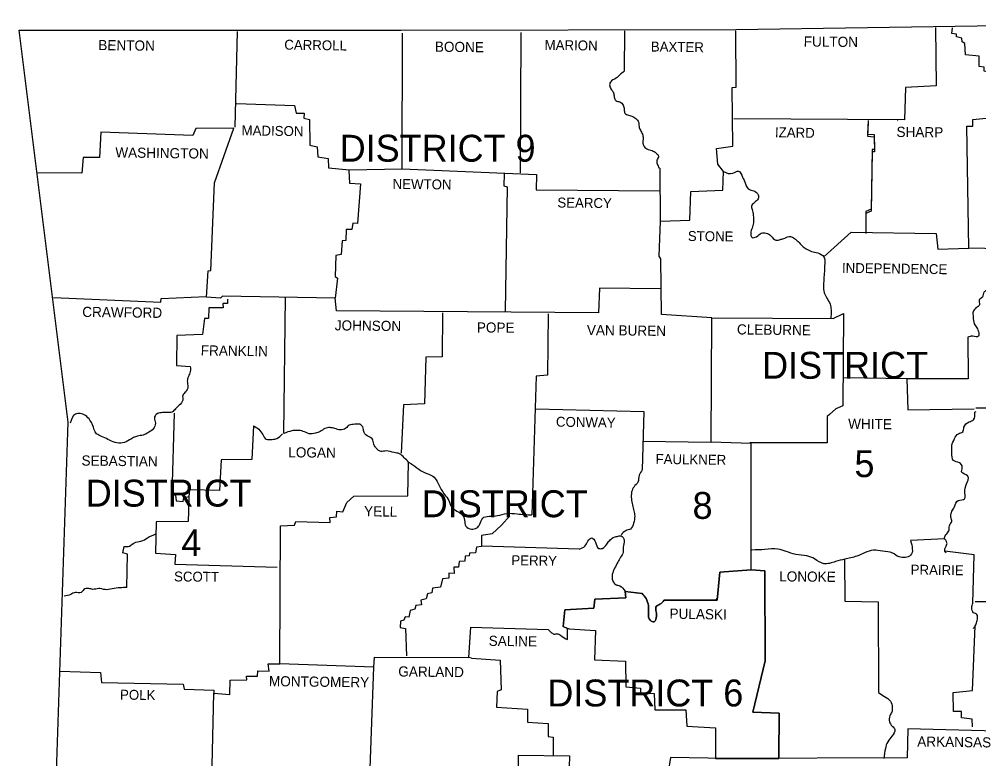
# Model space of a CAD drawing. Extents: x 1096785 to 1382432, y 216169 to 341661.
# Drawn here: x 1229111 to 1237243, y 286360 to 292630 of the extents above; entities that cross this region are included whole.
import ezdxf

# ---------------------------------------------------------------- set-up
doc = ezdxf.new("R2010")
doc.units = 0
for name, color, linetype in [('1', 7, 'Continuous'), ('21', 7, 'Continuous'), ('3', 7, 'Continuous')]:
    doc.layers.add(name, color=color, linetype=linetype)

msp = doc.modelspace()

# ---------------------------------------------------------------- linework, layer by layer
at = {"layer": '1'}
for p, q in [((1237219.2, 289336.3), (1237457.2, 289336.3)), ((1233771.2, 287462.3), (1233757.2, 287464.3)), ((1233757.2, 287464.3), (1233771.2, 287462.3)), ((1232945.2, 287214.3), (1232921.2, 287218.3)), ((1233635.2, 286396.3), (1233635, 286386.2)), ((1235011.2, 286364.3), (1235011.2, 286363.9)), ((1235011.2, 286364.3), (1235011.2, 286363.9)), ((1235011.2, 286363.9), (1235107.2, 286362.3)), ((1235107.2, 286362.3), (1235549.2, 286364)), ((1235549.2, 286378.3), (1235549.2, 286364)), ((1235549.2, 286364), (1235549.2, 286378.3))]:
    msp.add_line(p, q, dxfattribs=at)
for points in [[(1229111.2, 292538.3), (1232345.2, 292536.3), (1235183.2, 292542.3), (1238531.2, 292594.3), (1240083.2, 292630.3)], [(1229345.2, 283788.3), (1229525.2, 289214.3), (1229111.2, 292538.3)], [(1230957.2, 292526.3), (1230939.2, 291716.3)], [(1230953.2, 291914.3), (1231445.2, 291898.3), (1231457.2, 291834.3), (1231525.2, 291832.3), (1231523.2, 291792.3), (1231571.2, 291780.3), (1231575.2, 291562.3), (1231637.2, 291548.3), (1231641.2, 291462.3), (1231729.2, 291450.3), (1231733.2, 291370.3), (1231907.2, 291352.3), (1232355.2, 291362.3), (1232359.2, 292512.3)], [(1233361.2, 292516.3), (1233355.2, 291328.3)], [(1234241.2, 292530.3), (1234237.2, 292188.3)], [(1234577.2, 287704.3), (1235027.2, 287706.3), (1235047.2, 287942.3), (1235315.2, 287962.3), (1235315.2, 289034.3), (1234975.2, 289044.3), (1234981.2, 290098.3), (1234553.2, 290126.3), (1234547.2, 290598.3), (1234533.2, 290622.3), (1234545.2, 290918.3), (1234793.2, 290926.3), (1234803.2, 291170.3), (1235075.2, 291180.3), (1235079.2, 291338.3), (1235031.2, 291400.3), (1235019.2, 291534.3), (1235159.2, 291554.3), (1235153.2, 292052.3), (1235187.2, 292054.3), (1235183.2, 292530.3)], [(1236877.2, 292560.3), (1236881.2, 292064.3), (1236621.2, 292050.3), (1236613.2, 291778.3), (1235167.2, 291786.3)], [(1237443.2, 289324.3), (1237453.2, 289054.3), (1237979.2, 289068.3), (1237965.2, 290672.3), (1237159.2, 290690.3), (1237141.2, 291722.3), (1237193.2, 291724.3), (1237191.2, 291780.3), (1237361.2, 291796.3), (1237353.2, 292058.3), (1237321.2, 292064.3), (1237323.2, 292180.3), (1237287.2, 292190.3), (1237287.2, 292224.3), (1237245.2, 292230.3), (1237245.2, 292316.3), (1237131.2, 292328.3), (1237125.2, 292424.3), (1237103.2, 292438.3), (1237099.2, 292470.3), (1237053.2, 292480.3), (1237055.2, 292504.3), (1237015.2, 292510.3), (1237021.2, 292558.3)], [(1231799.2, 290158.3), (1231789.2, 290264.3), (1230835.2, 290282.3), (1230817.2, 290264.3), (1230699.2, 290274.3), (1230711.2, 290498.3), (1230735.2, 290500.3), (1230767.2, 291242.3), (1230929.2, 291706.3), (1230607.2, 291704.3), (1230583.2, 291644.3), (1229803.2, 291672.3), (1229791.2, 291458.3), (1229653.2, 291458.3), (1229643.2, 291326.3), (1229269.2, 291328.3)], [(1236305.2, 291772.3), (1236301.2, 291656.3), (1236357.2, 291652.3), (1236359.2, 291524.3), (1236339.2, 291524.3), (1236331.2, 291020.3), (1236285.2, 291000.3), (1236285.2, 290832.3)], [(1236305.2, 291754.3), (1236301.2, 291638.3), (1236357.2, 291634.3), (1236359.2, 291506.3), (1236339.2, 291506.3), (1236331.2, 291002.3), (1236285.2, 290982.3), (1236285.2, 290814.3)], [(1236555.2, 291768.3), (1236557.2, 291770.3)], [(1234545.2, 290918.3), (1234543.2, 291368.3)], [(1231903.2, 291348.3), (1231911.2, 291240.3), (1232003.2, 291234.3), (1231979.2, 290898.3), (1231937.2, 290900.3), (1231929.2, 290846.3), (1231881.2, 290846.3), (1231879.2, 290754.3), (1231849.2, 290752.3), (1231839.2, 290634.3), (1231795.2, 290628.3), (1231789.2, 290448.3), (1231809.2, 290434.3), (1231789.2, 290264.3)], [(1232355.2, 291362.3), (1233495.2, 291314.3), (1233493.2, 291184.3), (1234539.2, 291176.3)], [(1233221.2, 291320.3), (1233219.2, 291216.3), (1233245.2, 291210.3), (1233229.2, 290154.3)], [(1235933.2, 290618.3), (1236161.2, 290824.3), (1236881.2, 290814.3), (1236895.2, 290680.3), (1237157.2, 290690.3)], [(1234545.2, 290344.3), (1234029.2, 290350.3), (1234019.2, 290140.3), (1231799.2, 290158.3)], [(1229401.2, 290272.3), (1230311.2, 290230.3), (1230315.2, 290262.3), (1230695.2, 290280.3)], [(1230875.2, 290256.3), (1230875.2, 290220.3), (1230837.2, 290220.3), (1230839.2, 290184.3), (1230717.2, 290182.3), (1230715.2, 290092.3), (1230681.2, 290092.3), (1230663.2, 289958.3), (1230447.2, 289948.3), (1230445.2, 289694.3), (1230561.2, 289686.3)], [(1231355.2, 289118.3), (1231369.2, 290272.3)], [(1232697.2, 290142.3), (1232695.2, 289768.3), (1232557.2, 289766.3), (1232545.2, 289368.3), (1232369.2, 289362.3), (1232349.2, 288950.3)], [(1233593.2, 290132.3), (1233589.2, 289612.3), (1233493.2, 289604.3), (1233455.2, 288428.3)], [(1234981.2, 290098.3), (1236009.2, 290092.3), (1236097.2, 290134.3), (1236091.2, 289352.3), (1236031.2, 289326.3), (1235977.2, 289280.3), (1235959.2, 289262.3), (1235957.2, 289038.3), (1235303.2, 289038.3)], [(1237149.2, 289934.3), (1237153.2, 289582.3), (1236633.2, 289580.3), (1236099.2, 289590.3)], [(1236633.2, 289580.3), (1236641.2, 289318.3), (1237203.2, 289328.3)], [(1230425.2, 289290.3), (1230405.2, 288602.3), (1230435.2, 288594.3), (1230441.2, 288546.3), (1230501.2, 288542.3), (1230507.2, 288576.3), (1230555.2, 288584.3)], [(1233489.2, 289326.3), (1234403.2, 289304.3), (1234391.2, 288810.3)], [(1237219.2, 289302.3), (1237209.2, 289300.3)], [(1231097.2, 289182.3), (1231083.2, 288896.3), (1230823.2, 288894.3), (1230809.2, 288634.3), (1230551.2, 288640.3), (1230543.2, 288372.3), (1230273.2, 288370.3), (1230265.2, 288102.3), (1230435.2, 288092.3), (1230429.2, 288010.3), (1231297.2, 287986.3)], [(1234393.2, 289052.3), (1234975.2, 289044.3)], [(1237979.2, 289068.3), (1238009.2, 287972.3), (1237533.2, 287970.3), (1237531.2, 287926.3), (1237393.2, 287918.3), (1237381.2, 287690.3), (1237213.2, 287690.3)], [(1230739.2, 285932.3), (1230761.2, 286916.3), (1230897.2, 286904.3), (1230899.2, 287026.3), (1231039.2, 287030.3), (1231037.2, 287062.3), (1231131.2, 287062.3), (1231133.2, 287106.3), (1231229.2, 287104.3), (1231221.2, 287164.3), (1231321.2, 287166.3), (1231325.2, 288336.3), (1231445.2, 288340.3), (1231455.2, 288372.3), (1231745.2, 288364.3), (1231743.2, 288406.3), (1231801.2, 288412.3), (1231803.2, 288458.3), (1231853.2, 288454.3), (1231887.2, 288534.3), (1231947.2, 288586.3), (1232403.2, 288588.3), (1232411.2, 288876.3)], [(1233269.2, 288420.3), (1233197.2, 288342.3), (1233119.2, 288268.3), (1233029.2, 288254.3), (1233029.2, 288160.3), (1232985.2, 288154.3), (1232977.2, 288106.3), (1232927.2, 288102.3), (1232923.2, 288080.3), (1232889.2, 288078.3), (1232887.2, 288036.3), (1232839.2, 288034.3), (1232835.2, 287986.3), (1232795.2, 287986.3), (1232797.2, 287930.3), (1232753.2, 287934.3), (1232751.2, 287890.3), (1232697.2, 287886.3), (1232681.2, 287814.3), (1232613.2, 287808.3), (1232607.2, 287768.3), (1232571.2, 287758.3), (1232561.2, 287716.3), (1232515.2, 287706.3), (1232519.2, 287664.3), (1232473.2, 287660.3), (1232465.2, 287628.3), (1232423.2, 287616.3), (1232413.2, 287562.3), (1232381.2, 287564.3), (1232371.2, 287536.3), (1232341.2, 287526.3), (1232339.2, 287472.3), (1232385.2, 287464.3), (1232393.2, 287232.3)], [(1236955.2, 288224.3), (1236665.2, 288210.3)], [(1230023.2, 287812.3), (1230029.2, 288094.3), (1229989.2, 288106.3), (1230001.2, 288160.3)], [(1233855.2, 288136.3), (1233031.2, 288162.3)], [(1237191.2, 287680.3), (1237205.2, 288088.3), (1236955.2, 288120.3)], [(1236105.2, 288054.3), (1236109.2, 287696.3), (1236391.2, 287690.3), (1236393.2, 286922.3)], [(1235315.2, 287962.3), (1235047.2, 287942.3), (1235027.2, 287706.3), (1234577.2, 287704.3)], [(1235315.2, 287962.3), (1235431.2, 287954.3), (1235433.2, 287190.3), (1235329.2, 286756.3), (1235551.2, 286746.3), (1235549.2, 286378.3)], [(1235549.2, 286378.3), (1235551.2, 286746.3), (1235329.2, 286756.3), (1235433.2, 287190.3), (1235431.2, 287954.3), (1235315.2, 287962.3)], [(1233757.2, 287372.3), (1233757.2, 287464.3), (1233721.2, 287482.3), (1233735.2, 287622.3), (1233981.2, 287636.3), (1233989.2, 287714.3), (1234251.2, 287724.3), (1234245.2, 287778.3), (1234389.2, 287762.3)], [(1234389.2, 287762.3), (1234245.2, 287778.3), (1234251.2, 287724.3), (1233989.2, 287714.3), (1233981.2, 287636.3), (1233735.2, 287622.3), (1233721.2, 287482.3), (1233757.2, 287464.3)], [(1235017.2, 287708.3), (1235027.2, 287718.3)], [(1232117.2, 287136.3), (1232121.2, 287222.3), (1232921.2, 287218.3), (1232939.2, 287476.3), (1233593.2, 287456.3)], [(1237189.2, 286630.3), (1237187.2, 286696.3), (1237097.2, 286706.3), (1237095.2, 286762.3), (1237029.2, 286760.3), (1237025.2, 286922.3), (1237189.2, 286940.3), (1237213.2, 287488.3)], [(1233771.2, 287462.3), (1233995.2, 287448.3), (1233987.2, 287198.3), (1234249.2, 287188.3), (1234253.2, 286970.3), (1234377.2, 286960.3), (1234377.2, 286922.3), (1234493.2, 286914.3), (1234497.2, 286774.3), (1234761.2, 286774.3), (1234769.2, 286636.3), (1235013.2, 286624.3), (1235011.2, 286364.3)], [(1233771.2, 287462.3), (1233995.2, 287448.3), (1233987.2, 287198.3), (1234249.2, 287188.3), (1234253.2, 286970.3), (1234377.2, 286960.3), (1234377.2, 286922.3), (1234493.2, 286914.3), (1234497.2, 286774.3), (1234761.2, 286774.3), (1234769.2, 286636.3), (1235013.2, 286624.3), (1235011.2, 286364.3)], [(1232945.2, 287214.3), (1233187.2, 287196.3), (1233195.2, 286944.3), (1233161.2, 286932.3), (1233157.2, 286798.3), (1233419.2, 286780.3), (1233419.2, 286670.3), (1233593.2, 286660.3), (1233595.2, 286550.3), (1233637.2, 286544.3), (1233635.2, 286396.3)], [(1229455.2, 287104.3), (1229801.2, 287092.3), (1229809.2, 287008.3), (1230501.2, 286994.3), (1230509.2, 286950.3), (1230761.2, 286942.3), (1230759.2, 286904.3)], [(1232071.2, 285890.3), (1232117.2, 287136.3)], [(1237397.2, 286594.3), (1236641.2, 286614.3), (1236637.2, 286368.3), (1235107.2, 286362.3)], [(1232085.2, 286056.3), (1233229.2, 286040.3), (1233251.2, 286230.3), (1233341.2, 286230.3), (1233343.2, 286390.3), (1233775.2, 286384.3), (1233771.2, 286288.3), (1233883.2, 286280.3), (1233883.2, 286104.3), (1233955.2, 286098.3)], [(1235107.2, 286362.3), (1234629.2, 286370.3), (1234611.2, 286248.3), (1234145.2, 286234.3), (1234141.2, 286194.3), (1234075.2, 286182.3), (1234067.2, 286114.3), (1233955.2, 286098.3)]]:
    msp.add_lwpolyline(points, dxfattribs=at)
for points in [[(1234237.2, 292188.3), (1234201.2, 292158.3), (1234169.2, 292130.3), (1234121.2, 292096.3), (1234115.2, 292064.3), (1234131.2, 292032.3), (1234147.2, 292006.3), (1234153.2, 291970.3), (1234167.2, 291940.3), (1234201.2, 291928.3), (1234229.2, 291902.3), (1234239.2, 291866.3), (1234243.2, 291832.3), (1234275.2, 291816.3), (1234311.2, 291804.3), (1234345.2, 291780.3), (1234361.2, 291750.3), (1234365.2, 291712.3), (1234379.2, 291682.3), (1234395.2, 291646.3), (1234399.2, 291616.3), (1234395.2, 291586.3), (1234403.2, 291558.3), (1234429.2, 291530.3), (1234475.2, 291516.3), (1234507.2, 291496.3), (1234529.2, 291468.3), (1234515.2, 291434.3), (1234517.2, 291404.3), (1234535.2, 291368.3)], [(1235079.2, 291338.3), (1235159.2, 291324.3), (1235207.2, 291342.3), (1235241.2, 291290.3), (1235259.2, 291250.3), (1235289.2, 291192.3), (1235337.2, 291174.3), (1235373.2, 291142.3), (1235373.2, 291108.3), (1235341.2, 291076.3), (1235317.2, 291044.3), (1235325.2, 291006.3), (1235333.2, 290954.3), (1235333.2, 290904.3), (1235321.2, 290858.3), (1235311.2, 290816.3), (1235321.2, 290780.3), (1235359.2, 290786.3), (1235399.2, 290816.3), (1235441.2, 290816.3), (1235481.2, 290794.3), (1235523.2, 290756.3), (1235565.2, 290764.3), (1235599.2, 290774.3), (1235647.2, 290788.3), (1235681.2, 290770.3), (1235711.2, 290746.3), (1235747.2, 290708.3), (1235781.2, 290684.3), (1235825.2, 290662.3), (1235879.2, 290648.3), (1235929.2, 290614.3), (1235937.2, 290556.3), (1235935.2, 290506.3), (1235931.2, 290444.3), (1235927.2, 290376.3), (1235933.2, 290310.3), (1235955.2, 290266.3), (1235983.2, 290214.3), (1235991.2, 290166.3), (1235989.2, 290090.3)], [(1237507.2, 290654.3), (1237483.2, 290592.3), (1237455.2, 290532.3), (1237437.2, 290480.3), (1237399.2, 290450.3), (1237387.2, 290422.3), (1237353.2, 290410.3), (1237327.2, 290370.3), (1237315.2, 290334.3), (1237287.2, 290318.3), (1237273.2, 290274.3), (1237247.2, 290250.3), (1237249.2, 290210.3), (1237219.2, 290182.3), (1237195.2, 290150.3), (1237195.2, 290106.3), (1237205.2, 290048.3), (1237225.2, 290014.3), (1237243.2, 289970.3), (1237241.2, 289942.3), (1237191.2, 289942.3), (1237149.2, 289934.3)], [(1230561.2, 289686.3), (1230561.2, 289644.3), (1230545.2, 289600.3), (1230535.2, 289562.3), (1230541.2, 289512.3), (1230523.2, 289472.3), (1230497.2, 289440.3), (1230497.2, 289400.3), (1230467.2, 289358.3), (1230435.2, 289326.3), (1230407.2, 289300.3), (1230357.2, 289296.3), (1230315.2, 289294.3), (1230273.2, 289280.3), (1230257.2, 289250.3), (1230265.2, 289204.3), (1230249.2, 289160.3), (1230207.2, 289126.3), (1230161.2, 289104.3), (1230113.2, 289096.3), (1230047.2, 289064.3), (1229987.2, 289038.3), (1229923.2, 289042.3), (1229863.2, 289068.3), (1229809.2, 289092.3), (1229767.2, 289116.3), (1229733.2, 289190.3), (1229711.2, 289230.3), (1229673.2, 289270.3), (1229627.2, 289286.3), (1229589.2, 289282.3), (1229543.2, 289204.3)], [(1236965.2, 288106.3), (1236955.2, 288120.3), (1236967.2, 288164.3), (1236973.2, 288192.3), (1236953.2, 288232.3), (1236971.2, 288266.3), (1236991.2, 288302.3), (1236997.2, 288344.3), (1237013.2, 288372.3), (1237007.2, 288408.3), (1237015.2, 288458.3), (1237037.2, 288496.3), (1237069.2, 288550.3), (1237123.2, 288564.3), (1237127.2, 288586.3), (1237125.2, 288636.3), (1237147.2, 288710.3), (1237155.2, 288736.3), (1237147.2, 288760.3), (1237099.2, 288788.3), (1237103.2, 288830.3), (1237079.2, 288870.3), (1237029.2, 288888.3), (1237015.2, 288956.3), (1237015.2, 289016.3), (1237037.2, 289074.3), (1237071.2, 289116.3), (1237107.2, 289132.3), (1237117.2, 289172.3), (1237161.2, 289216.3), (1237199.2, 289234.3), (1237209.2, 289300.3)], [(1231097.2, 289182.3), (1231141.2, 289154.3), (1231175.2, 289108.3), (1231205.2, 289070.3), (1231255.2, 289068.3), (1231295.2, 289076.3), (1231341.2, 289116.3)], [(1232411.2, 288876.3), (1232373.2, 288912.3), (1232333.2, 288946.3), (1232289.2, 288956.3), (1232221.2, 288970.3), (1232177.2, 288966.3), (1232151.2, 288978.3), (1232133.2, 288998.3), (1232115.2, 289028.3), (1232105.2, 289070.3), (1232071.2, 289092.3), (1232033.2, 289126.3), (1232027.2, 289162.3), (1231997.2, 289196.3), (1231955.2, 289196.3), (1231907.2, 289188.3), (1231879.2, 289162.3), (1231831.2, 289148.3), (1231787.2, 289160.3), (1231745.2, 289168.3), (1231701.2, 289160.3), (1231661.2, 289134.3), (1231621.2, 289120.3), (1231567.2, 289116.3), (1231517.2, 289136.3), (1231469.2, 289144.3), (1231421.2, 289140.3), (1231355.2, 289118.3)], [(1232411.2, 288876.3), (1232481.2, 288828.3), (1232547.2, 288786.3), (1232615.2, 288756.3), (1232653.2, 288712.3), (1232687.2, 288644.3), (1232715.2, 288602.3), (1232751.2, 288550.3), (1232777.2, 288492.3), (1232819.2, 288460.3), (1232863.2, 288432.3), (1232885.2, 288382.3), (1232895.2, 288332.3), (1232943.2, 288308.3), (1232989.2, 288318.3), (1233015.2, 288348.3), (1233039.2, 288400.3), (1233093.2, 288416.3), (1233163.2, 288422.3), (1233243.2, 288440.3), (1233331.2, 288436.3), (1233455.2, 288428.3)], [(1234391.2, 288810.3), (1234365.2, 288764.3), (1234353.2, 288704.3), (1234321.2, 288666.3), (1234301.2, 288622.3), (1234299.2, 288564.3), (1234309.2, 288512.3), (1234319.2, 288462.3), (1234327.2, 288416.3), (1234317.2, 288358.3), (1234291.2, 288308.3), (1234251.2, 288294.3), (1234213.2, 288260.3)], [(1230001.2, 288160.3), (1230045.2, 288164.3), (1230087.2, 288192.3), (1230143.2, 288204.3), (1230199.2, 288234.3), (1230269.2, 288266.3)], [(1233855.2, 288136.3), (1233905.2, 288164.3), (1233931.2, 288206.3), (1233963.2, 288232.3), (1233995.2, 288196.3), (1234023.2, 288144.3), (1234053.2, 288144.3), (1234091.2, 288180.3), (1234115.2, 288212.3), (1234145.2, 288236.3), (1234177.2, 288246.3), (1234211.2, 288250.3), (1234237.2, 288212.3), (1234229.2, 288152.3), (1234229.2, 288112.3), (1234207.2, 288070.3), (1234183.2, 288026.3), (1234157.2, 287976.3), (1234137.2, 287922.3), (1234141.2, 287870.3), (1234169.2, 287836.3), (1234201.2, 287826.3), (1234245.2, 287782.3)], [(1236665.2, 288210.3), (1236665.2, 288086.3), (1236567.2, 288072.3), (1236513.2, 288104.3), (1236427.2, 288120.3), (1236351.2, 288130.3), (1236275.2, 288106.3), (1236209.2, 288078.3), (1236107.2, 288052.3), (1236029.2, 288032.3), (1235929.2, 288014.3), (1235851.2, 288054.3), (1235785.2, 288080.3), (1235691.2, 288092.3), (1235611.2, 288118.3), (1235541.2, 288138.3), (1235431.2, 288134.3), (1235319.2, 288130.3)], [(1230023.2, 287812.3), (1229965.2, 287810.3), (1229899.2, 287802.3), (1229839.2, 287794.3), (1229785.2, 287804.3), (1229735.2, 287796.3), (1229701.2, 287804.3), (1229659.2, 287794.3), (1229635.2, 287770.3), (1229585.2, 287770.3), (1229549.2, 287754.3), (1229491.2, 287740.3)], [(1234389.2, 287762.3), (1234423.2, 287718.3), (1234443.2, 287658.3), (1234443.2, 287590.3), (1234459.2, 287534.3), (1234491.2, 287522.3), (1234511.2, 287570.3), (1234507.2, 287618.3), (1234507.2, 287646.3), (1234541.2, 287670.3), (1234577.2, 287704.3)], [(1234577.2, 287704.3), (1234541.2, 287670.3), (1234507.2, 287646.3), (1234507.2, 287618.3), (1234511.2, 287570.3), (1234491.2, 287522.3), (1234459.2, 287534.3), (1234443.2, 287590.3), (1234443.2, 287658.3), (1234423.2, 287718.3), (1234389.2, 287762.3)], [(1237195.2, 287464.3), (1237213.2, 287488.3), (1237221.2, 287504.3), (1237231.2, 287544.3), (1237227.2, 287584.3), (1237199.2, 287598.3), (1237183.2, 287640.3), (1237191.2, 287680.3)], [(1233593.2, 287456.3), (1233617.2, 287434.3), (1233643.2, 287418.3), (1233675.2, 287420.3), (1233705.2, 287402.3), (1233757.2, 287372.3)], [(1236393.2, 286922.3), (1236443.2, 286888.3), (1236495.2, 286848.3), (1236509.2, 286794.3), (1236505.2, 286756.3), (1236489.2, 286724.3), (1236485.2, 286674.3), (1236509.2, 286638.3), (1236531.2, 286608.3), (1236509.2, 286554.3), (1236471.2, 286504.3), (1236451.2, 286448.3), (1236437.2, 286364.3)]]:
    msp.add_spline(points, degree=3, dxfattribs=at)
at = {"layer": '21'}
msp.add_lwpolyline([(1232117.2, 287136.3), (1231321.2, 287166.3)], dxfattribs=at)

# ---------------------------------------------------------------- texts
for s, p in [('DISTRICT 9', (1231827.2, 291422.3)), ('DISTRICT', (1235407.2, 289582.3)), ('5', (1236189.2, 288748.3)), ('DISTRICT', (1229675.2, 288498.3)), ('DISTRICT', (1232523.2, 288408.3)), ('8', (1234817.2, 288394.3)), ('4', (1230485.2, 288078.3)), ('DISTRICT 6', (1233587.2, 286804.3))]:
    msp.add_text(s, height=228, dxfattribs=at).set_placement(p)
at = {"layer": '3'}
for s, height, rotation, p in [('BENTON', 86.02, 359.25271, (1229781.2, 292368.3)), ('CARROLL', 84.01, 359.14808, (1231357.2, 292372.3)), ('BOONE', 86.02, 359.40007, (1232633.2, 292354.3)), ('MARION', 84.01, 359.18542, (1233563.2, 292370.3)), ('BAXTER', 84.01, 359.25594, (1234463.2, 292356.3)), ('FULTON', 85.99, 359.49961, (1235759.2, 292398.3)), ('MADISON', 84.01, 359.09062, (1230995.2, 291646.3)), ('IZARD', 83.99, 358.92583, (1235515.2, 291630.3)), ('SHARP', 85.99, 359.39049, (1236545.2, 291632.3)), ('WASHINGTON', 85.99, 359.23201, (1229925.2, 291458.3)), ('NEWTON', 84.01, 359.2717, (1232275.2, 291192.3)), ('SEARCY', 83.99, 359.25271, (1233671.2, 291034.3)), ('STONE', 83.99, 359.40007, (1234777.2, 290750.3)), ('INDEPENDENCE', 83.988, 359.21874, (1236083.2, 290480.3)), ('CRAWFORD', 85.99, 359.27706, (1229645.2, 290106.3)), ('JOHNSON', 86.02, 359.3514, (1231785.2, 289992.3)), ('POPE', 86.02, 359.61547, (1232989.2, 289974.3)), ('VAN BUREN', 86.02, 359.35078, (1233921.2, 289952.3)), ('CLEBURNE', 85.99, 359.25352, (1235193.2, 289958.3)), ('FRANKLIN', 86.02, 359.18154, (1230649.2, 289780.3)), ('CONWAY', 83.99, 359.03714, (1233659.2, 289176.3)), ('WHITE', 86.02, 359.31386, (1236135.2, 289158.3)), ('SEBASTIAN', 85.99, 359.28159, (1229639.2, 288846.3)), ('LOGAN', 86.02, 359.39691, (1231391.2, 288916.3)), ('FAULKNER', 84.01, 359.24862, (1234503.2, 288860.3)), ('YELL', 86.02, 359.19871, (1232033.2, 288416.3)), ('PERRY', 84.01, 359.08578, (1233281.2, 288002.3)), ('PRAIRIE', 84.01, 359.21158, (1236665.2, 287922.3)), ('SCOTT', 84.01, 359.40628, (1230423.2, 287864.3)), ('LONOKE', 86.02, 359.49742, (1235551.2, 287864.3)), ('PULASKI', 86.02, 359.05305, (1234621.2, 287548.3)), ('SALINE', 86.02, 359.14914, (1233089.2, 287318.3)), ('GARLAND', 86.02, 359.36576, (1232323.2, 287058.3)), ('MONTGOMERY', 86.02, 359.29442, (1231227.2, 286976.3)), ('POLK', 83.99, 359.21517, (1229965.2, 286862.3)), ('ARKANSAS', 85.99, 359.26783, (1236721.2, 286464.3))]:
    msp.add_text(s, height=height, rotation=rotation, dxfattribs=at).set_placement(p)

doc.saveas('drawing.dxf')
